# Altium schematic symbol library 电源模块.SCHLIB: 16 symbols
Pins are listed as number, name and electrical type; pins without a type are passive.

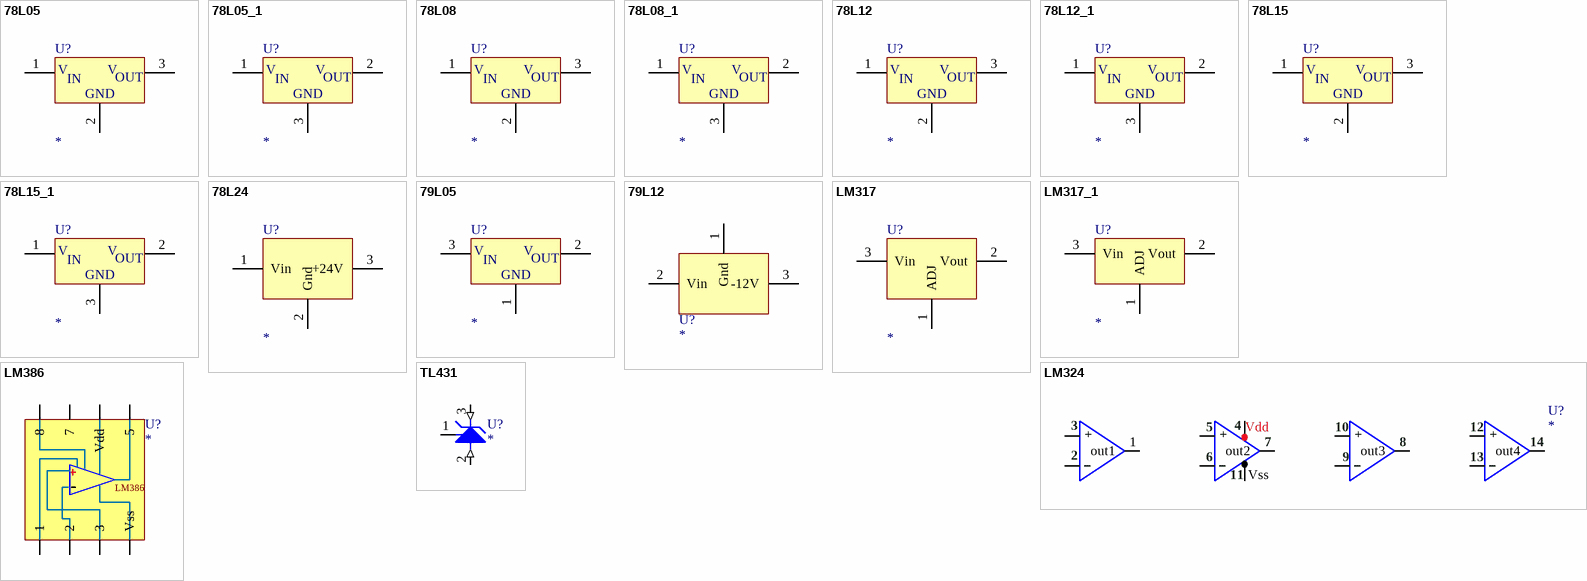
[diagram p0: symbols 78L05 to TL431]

## 78L05
designator U?
3-Terminal Positive Voltage Regulator
footprint 78XX
simulation model 78L05 (SUBCKT)
pins: 1 VIN, 2 GND, 3 VOUT

## 78L05_1
designator U?
3-Terminal Positive Voltage Regulator
simulation model 78L05 (SUBCKT)
pins: 1 VIN, 2 VOUT, 3 GND

## 78L08
designator U?
3-Terminal Positive Voltage Regulator
footprint 78XX
simulation model 78L08 (SUBCKT)
pins: 1 VIN, 2 GND, 3 VOUT

## 78L08_1
designator U?
3-Terminal Positive Voltage Regulator
simulation model 78L08 (SUBCKT)
pins: 1 VIN, 2 VOUT, 3 GND

## 78L12
designator U?
3-Terminal Positive Voltage Regulator
footprint 78XX
simulation model 78L12 (SUBCKT)
pins: 1 VIN, 2 GND, 3 VOUT

## 78L12_1
designator U?
3-Terminal Positive Voltage Regulator
simulation model 78L12 (SUBCKT)
pins: 1 VIN, 2 VOUT, 3 GND

## 78L15
designator U?
3-Terminal Positive Voltage Regulator
footprint 78XX
simulation model 78L15 (SUBCKT)
pins: 1 VIN, 2 GND, 3 VOUT

## 78L15_1
designator U?
3-Terminal Positive Voltage Regulator
simulation model 78L15 (SUBCKT)
pins: 1 VIN, 2 VOUT, 3 GND

## 78L24
designator U?
footprint TO-220
pins: 1 Vin, 2 Gnd, 3 +24V

## 79L05
designator U?
pins: 1 GND, 2 VOUT, 3 VIN

## 79L12
designator U?
footprint TO-220
pins: 1 Gnd, 2 Vin, 3 -12V

## LM317
designator U?
pins: 1 ADJ, 2 Vout, 3 Vin

## LM317_1
designator U?
3-Terminal Adjustable Positive Voltage Regulator
simulation model LM317 (SUBCKT)
pins: 1 ADJ, 2 Vout, 3 Vin

## LM324
designator U?
pins: 1 out1, 2, 3, 4, 5, 6, 7 out2, 8 out3, 9, 10, 11, 12, 13, 14 out4

## LM386
designator U?
pins: 1, 2, 3, 4 Vss, 5, 6 Vdd, 7, 8

## TL431
designator U?
Adjustable Precision Shunt Regulator
simulation model TL431 (SUBCKT)
pins: 1 R, 2 A (in), 3 K (in)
